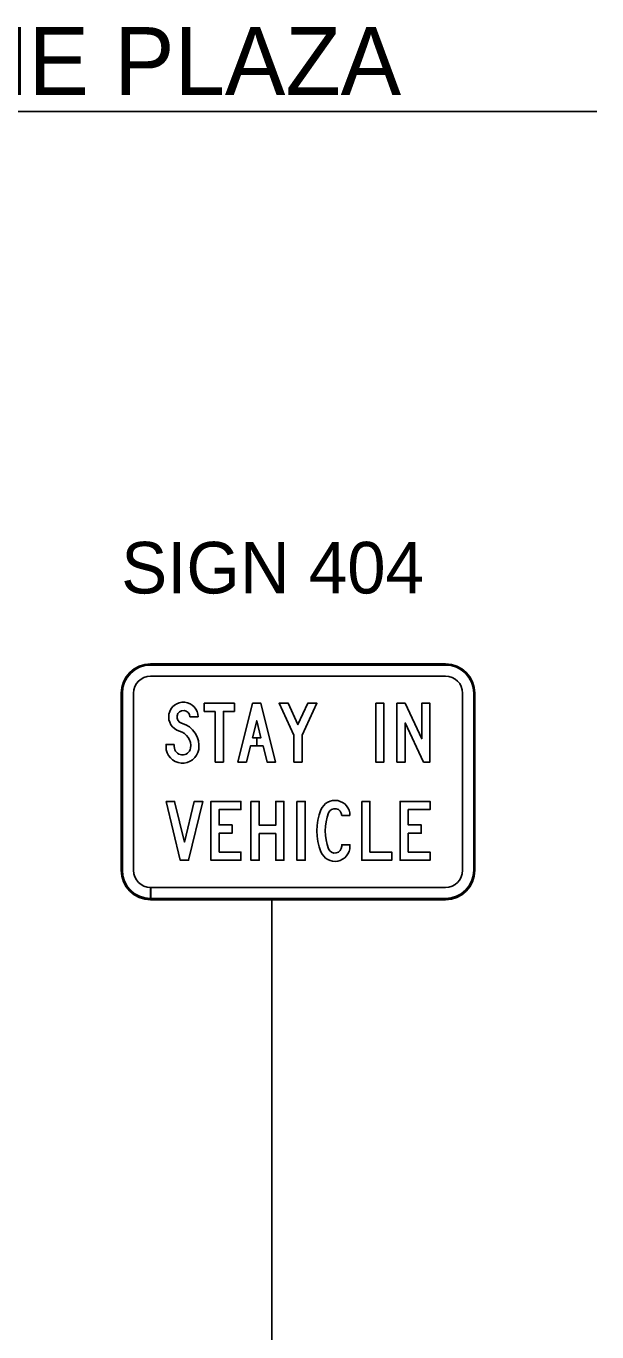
# Model space of a CAD drawing. Extents: x 524708 to 525490, y 1531861 to 1532506.
# Drawn here: x 525153.9 to 525192.6, y 1532090 to 1532178.6 of the extents above; entities that cross this region are included whole.
import ezdxf

# ---------------------------------------------------------------- set-up
doc = ezdxf.new("R2010")
doc.units = 0
for name, color, linetype in [('GSBWFill', 7, 'Continuous'), ('GSColorFill', 7, 'Continuous'), ('GSOutline', 7, 'Continuous'), ('LeaderLine_dp', 7, 'Continuous'), ('TextDetails', 7, 'Continuous'), ('TextLabel', 7, 'Continuous')]:
    doc.layers.add(name, color=color, linetype=linetype)

msp = doc.modelspace()

# ---------------------------------------------------------------- linework, layer by layer
at = {"layer": 'GSBWFill'}
for p, q in [((525164.979, 1532131.74), (525165.539, 1532131.74)), ((525163.919, 1532129.72), (525163.919, 1532129.87)), ((525175.287, 1532125.054), (525175.847, 1532125.054))]:
    msp.add_line(p, q, dxfattribs=at)
for points in [[(525166.699, 1532132.11), (525165.959, 1532132.11), (525165.959, 1532132.67), (525167.999, 1532132.67), (525167.999, 1532132.11), (525167.259, 1532132.11), (525167.259, 1532128.67), (525166.699, 1532128.67)], [(525169.519, 1532130.33), (525169.232, 1532130.33), (525169.519, 1532131.481), (525169.807, 1532130.33), (525169.52, 1532130.33), (525169.52, 1532129.77), (525169.947, 1532129.77), (525170.222, 1532128.67), (525170.799, 1532128.67), (525169.799, 1532132.67), (525169.239, 1532132.67), (525168.239, 1532128.67), (525168.817, 1532128.67), (525169.092, 1532129.77), (525169.519, 1532129.77)], [(525172.039, 1532130.49), (525172.039, 1532128.67), (525172.599, 1532128.67), (525172.599, 1532130.49), (525173.599, 1532132.67), (525172.983, 1532132.67), (525172.319, 1532131.223), (525171.655, 1532132.67), (525171.039, 1532132.67)], [(525177.599, 1532132.67), (525178.159, 1532132.67), (525178.159, 1532128.67), (525177.599, 1532128.67)], [(525180.839, 1532128.67), (525181.279, 1532128.67), (525181.279, 1532132.67), (525180.719, 1532132.67), (525180.719, 1532130.253), (525179.593, 1532132.67), (525179.039, 1532132.67), (525179.039, 1532128.67), (525179.599, 1532128.67), (525179.599, 1532131.33)], [(525163.367, 1532126.004), (525163.943, 1532126.004), (525164.607, 1532123.237), (525165.271, 1532126.004), (525165.847, 1532126.004), (525164.887, 1532122.004), (525164.327, 1532122.004)], [(525166.967, 1532122.564), (525166.967, 1532123.844), (525167.844, 1532123.844), (525167.844, 1532124.404), (525166.967, 1532124.404), (525166.967, 1532125.444), (525168.447, 1532125.444), (525168.447, 1532126.004), (525166.407, 1532126.004), (525166.407, 1532122.004), (525168.447, 1532122.004), (525168.447, 1532122.564)], [(525169.127, 1532126.004), (525169.687, 1532126.004), (525169.687, 1532124.384), (525170.807, 1532124.384), (525170.807, 1532126.004), (525171.367, 1532126.004), (525171.367, 1532122.004), (525170.807, 1532122.004), (525170.807, 1532123.824), (525169.687, 1532123.824), (525169.687, 1532122.004), (525169.127, 1532122.004)], [(525172.247, 1532126.004), (525172.807, 1532126.004), (525172.807, 1532122.004), (525172.247, 1532122.004)], [(525176.647, 1532126.004), (525177.207, 1532126.004), (525177.207, 1532122.564), (525178.687, 1532122.564), (525178.687, 1532122.004), (525176.647, 1532122.004)], [(525179.807, 1532122.564), (525179.807, 1532123.844), (525180.684, 1532123.844), (525180.684, 1532124.404), (525179.807, 1532124.404), (525179.807, 1532125.444), (525181.287, 1532125.444), (525181.287, 1532126.004), (525179.247, 1532126.004), (525179.247, 1532122.004), (525181.287, 1532122.004), (525181.287, 1532122.564)]]:
    msp.add_lwpolyline(points, close=True, dxfattribs=at)
for points in [[(525163.919, 1532129.87), (525163.359, 1532129.87), (525163.359, 1532129.72)], [(525175.847, 1532122.954), (525175.847, 1532123.064), (525175.287, 1532123.064), (525175.287, 1532122.954)]]:
    msp.add_lwpolyline(points, dxfattribs=at)
for centre, radius, start, end in [((525164.539, 1532131.74), 1, 0, 254.22594), ((525164.539, 1532131.74), 0.44, 0, 254.22594), ((525163.979, 1532129.758), 1.62, 352.12977, 74.22594), ((525163.979, 1532129.758), 1.06, 352.58042, 74.22594), ((525164.479, 1532129.72), 1.12, 180, 350.53133), ((525164.479, 1532129.72), 0.56, 180, 349.78566), ((525174.827, 1532125.054), 1.02, 0, 158.43141), ((525177.484, 1532124.004), 3.876, 158.43141, 201.5686), ((525177.484, 1532124.004), 3.316, 158.4314, 201.56859), ((525174.827, 1532125.054), 0.46, 0, 158.43141), ((525174.827, 1532122.954), 1.02, 201.56859, 0), ((525174.827, 1532122.954), 0.46, 201.56859, 0)]:
    msp.add_arc(centre, radius, start, end, dxfattribs=at)
at = {"layer": 'GSColorFill'}
for p, q in [((525182.331, 1532135.345), (525162.315, 1532135.345)), ((525182.331, 1532135.345), (525162.315, 1532135.345)), ((525182.331, 1532135.345), (525162.315, 1532135.345)), ((525162.315, 1532135.262), (525182.331, 1532135.262)), ((525162.315, 1532134.512), (525182.331, 1532134.512)), ((525160.315, 1532133.345), (525160.315, 1532121.329)), ((525160.315, 1532133.345), (525160.315, 1532121.329)), ((525160.315, 1532133.345), (525160.315, 1532121.329)), ((525160.399, 1532121.329), (525160.399, 1532133.345)), ((525161.149, 1532121.329), (525161.149, 1532133.345)), ((525183.498, 1532133.345), (525183.498, 1532121.329)), ((525184.248, 1532133.345), (525184.248, 1532121.329)), ((525184.331, 1532121.329), (525184.331, 1532133.345)), ((525184.331, 1532121.329), (525184.331, 1532133.345)), ((525184.331, 1532121.329), (525184.331, 1532133.345)), ((525164.979, 1532131.74), (525165.539, 1532131.74)), ((525163.919, 1532129.72), (525163.919, 1532129.87)), ((525175.287, 1532125.054), (525175.847, 1532125.054)), ((525162.315, 1532119.329), (525162.315, 1532120.162)), ((525162.315, 1532119.329), (525162.315, 1532119.412)), ((525182.331, 1532119.412), (525162.316, 1532119.412)), ((525162.316, 1532119.412), (525162.316, 1532119.329)), ((525182.331, 1532120.162), (525162.324, 1532120.162)), ((525162.324, 1532120.162), (525162.324, 1532119.329)), ((525162.315, 1532119.329), (525182.331, 1532119.329)), ((525162.316, 1532119.329), (525182.331, 1532119.329)), ((525162.324, 1532119.329), (525182.331, 1532119.329))]:
    msp.add_line(p, q, dxfattribs=at)
for points in [[(525166.699, 1532132.11), (525165.959, 1532132.11), (525165.959, 1532132.67), (525167.999, 1532132.67), (525167.999, 1532132.11), (525167.259, 1532132.11), (525167.259, 1532128.67), (525166.699, 1532128.67)], [(525169.519, 1532130.33), (525169.232, 1532130.33), (525169.519, 1532131.481), (525169.807, 1532130.33), (525169.52, 1532130.33), (525169.52, 1532129.77), (525169.947, 1532129.77), (525170.222, 1532128.67), (525170.799, 1532128.67), (525169.799, 1532132.67), (525169.239, 1532132.67), (525168.239, 1532128.67), (525168.817, 1532128.67), (525169.092, 1532129.77), (525169.519, 1532129.77)], [(525172.039, 1532130.49), (525172.039, 1532128.67), (525172.599, 1532128.67), (525172.599, 1532130.49), (525173.599, 1532132.67), (525172.983, 1532132.67), (525172.319, 1532131.223), (525171.655, 1532132.67), (525171.039, 1532132.67)], [(525177.599, 1532132.67), (525178.159, 1532132.67), (525178.159, 1532128.67), (525177.599, 1532128.67)], [(525180.839, 1532128.67), (525181.279, 1532128.67), (525181.279, 1532132.67), (525180.719, 1532132.67), (525180.719, 1532130.253), (525179.593, 1532132.67), (525179.039, 1532132.67), (525179.039, 1532128.67), (525179.599, 1532128.67), (525179.599, 1532131.33)], [(525163.367, 1532126.004), (525163.943, 1532126.004), (525164.607, 1532123.237), (525165.271, 1532126.004), (525165.847, 1532126.004), (525164.887, 1532122.004), (525164.327, 1532122.004)], [(525166.967, 1532122.564), (525166.967, 1532123.844), (525167.844, 1532123.844), (525167.844, 1532124.404), (525166.967, 1532124.404), (525166.967, 1532125.444), (525168.447, 1532125.444), (525168.447, 1532126.004), (525166.407, 1532126.004), (525166.407, 1532122.004), (525168.447, 1532122.004), (525168.447, 1532122.564)], [(525169.127, 1532126.004), (525169.687, 1532126.004), (525169.687, 1532124.384), (525170.807, 1532124.384), (525170.807, 1532126.004), (525171.367, 1532126.004), (525171.367, 1532122.004), (525170.807, 1532122.004), (525170.807, 1532123.824), (525169.687, 1532123.824), (525169.687, 1532122.004), (525169.127, 1532122.004)], [(525172.247, 1532126.004), (525172.807, 1532126.004), (525172.807, 1532122.004), (525172.247, 1532122.004)], [(525176.647, 1532126.004), (525177.207, 1532126.004), (525177.207, 1532122.564), (525178.687, 1532122.564), (525178.687, 1532122.004), (525176.647, 1532122.004)], [(525179.807, 1532122.564), (525179.807, 1532123.844), (525180.684, 1532123.844), (525180.684, 1532124.404), (525179.807, 1532124.404), (525179.807, 1532125.444), (525181.287, 1532125.444), (525181.287, 1532126.004), (525179.247, 1532126.004), (525179.247, 1532122.004), (525181.287, 1532122.004), (525181.287, 1532122.564)]]:
    msp.add_lwpolyline(points, close=True, dxfattribs=at)
for points in [[(525163.919, 1532129.87), (525163.359, 1532129.87), (525163.359, 1532129.72)], [(525175.847, 1532122.954), (525175.847, 1532123.064), (525175.287, 1532123.064), (525175.287, 1532122.954)]]:
    msp.add_lwpolyline(points, dxfattribs=at)
for centre, radius, start, end in [((525162.315, 1532133.345), 2, 90, 180), ((525162.315, 1532133.345), 2, 90, 180), ((525162.315, 1532133.345), 2, 90, 180), ((525162.315, 1532133.345), 1.917, 90, 180), ((525162.315, 1532133.345), 1.167, 90, 180), ((525182.331, 1532133.345), 2, 0, 90), ((525182.331, 1532133.345), 2, 0, 90), ((525182.331, 1532133.345), 2, 0, 90), ((525182.331, 1532133.345), 1.917, 0, 90), ((525182.331, 1532133.345), 1.167, 0, 90), ((525164.539, 1532131.74), 1, 0, 254.22594), ((525164.539, 1532131.74), 0.44, 0, 254.22594), ((525163.979, 1532129.758), 1.62, 352.12977, 74.22594), ((525163.979, 1532129.758), 1.06, 352.58042, 74.22594), ((525164.479, 1532129.72), 1.12, 180, 350.53133), ((525164.479, 1532129.72), 0.56, 180, 349.78566), ((525174.827, 1532125.054), 1.02, 0, 158.43141), ((525177.484, 1532124.004), 3.876, 158.43141, 201.5686), ((525177.484, 1532124.004), 3.316, 158.4314, 201.56859), ((525174.827, 1532125.054), 0.46, 0, 158.43141), ((525174.827, 1532122.954), 1.02, 201.56859, 0), ((525174.827, 1532122.954), 0.46, 201.56859, 0), ((525162.315, 1532121.329), 2, 180, 270), ((525162.315, 1532121.329), 2, 180, 270), ((525162.315, 1532121.329), 2, 180, 270), ((525162.315, 1532121.329), 1.917, 180, 270), ((525162.315, 1532121.329), 1.167, 180, 270), ((525182.331, 1532121.329), 2, 270, 0), ((525182.331, 1532121.329), 1.167, 270, 0), ((525182.331, 1532121.329), 2, 270, 0), ((525182.331, 1532121.329), 1.917, 270, 0), ((525182.331, 1532121.329), 2, 270, 0)]:
    msp.add_arc(centre, radius, start, end, dxfattribs=at)
at = {"layer": 'GSOutline'}
for p, q in [((525164.979, 1532131.74), (525165.539, 1532131.74)), ((525163.919, 1532129.72), (525163.919, 1532129.87)), ((525175.287, 1532125.054), (525175.847, 1532125.054))]:
    msp.add_line(p, q, dxfattribs=at)
for points in [[(525166.699, 1532132.11), (525165.959, 1532132.11), (525165.959, 1532132.67), (525167.999, 1532132.67), (525167.999, 1532132.11), (525167.259, 1532132.11), (525167.259, 1532128.67), (525166.699, 1532128.67)], [(525169.092, 1532129.77), (525169.947, 1532129.77), (525170.222, 1532128.67), (525170.799, 1532128.67), (525169.799, 1532132.67), (525169.239, 1532132.67), (525168.239, 1532128.67), (525168.817, 1532128.67)], [(525172.039, 1532130.49), (525172.039, 1532128.67), (525172.599, 1532128.67), (525172.599, 1532130.49), (525173.599, 1532132.67), (525172.983, 1532132.67), (525172.319, 1532131.223), (525171.655, 1532132.67), (525171.039, 1532132.67)], [(525177.599, 1532132.67), (525178.159, 1532132.67), (525178.159, 1532128.67), (525177.599, 1532128.67)], [(525180.839, 1532128.67), (525181.279, 1532128.67), (525181.279, 1532132.67), (525180.719, 1532132.67), (525180.719, 1532130.253), (525179.593, 1532132.67), (525179.039, 1532132.67), (525179.039, 1532128.67), (525179.599, 1532128.67), (525179.599, 1532131.33)], [(525169.807, 1532130.33), (525169.519, 1532131.481), (525169.232, 1532130.33)], [(525163.367, 1532126.004), (525163.943, 1532126.004), (525164.607, 1532123.237), (525165.271, 1532126.004), (525165.847, 1532126.004), (525164.887, 1532122.004), (525164.327, 1532122.004)], [(525166.967, 1532122.564), (525166.967, 1532123.844), (525167.844, 1532123.844), (525167.844, 1532124.404), (525166.967, 1532124.404), (525166.967, 1532125.444), (525168.447, 1532125.444), (525168.447, 1532126.004), (525166.407, 1532126.004), (525166.407, 1532122.004), (525168.447, 1532122.004), (525168.447, 1532122.564)], [(525169.127, 1532126.004), (525169.687, 1532126.004), (525169.687, 1532124.384), (525170.807, 1532124.384), (525170.807, 1532126.004), (525171.367, 1532126.004), (525171.367, 1532122.004), (525170.807, 1532122.004), (525170.807, 1532123.824), (525169.687, 1532123.824), (525169.687, 1532122.004), (525169.127, 1532122.004)], [(525172.247, 1532126.004), (525172.807, 1532126.004), (525172.807, 1532122.004), (525172.247, 1532122.004)], [(525176.647, 1532126.004), (525177.207, 1532126.004), (525177.207, 1532122.564), (525178.687, 1532122.564), (525178.687, 1532122.004), (525176.647, 1532122.004)], [(525179.807, 1532122.564), (525179.807, 1532123.844), (525180.684, 1532123.844), (525180.684, 1532124.404), (525179.807, 1532124.404), (525179.807, 1532125.444), (525181.287, 1532125.444), (525181.287, 1532126.004), (525179.247, 1532126.004), (525179.247, 1532122.004), (525181.287, 1532122.004), (525181.287, 1532122.564)]]:
    msp.add_lwpolyline(points, close=True, dxfattribs=at)
for points in [[(525163.919, 1532129.87), (525163.359, 1532129.87), (525163.359, 1532129.72)], [(525175.847, 1532122.954), (525175.847, 1532123.064), (525175.287, 1532123.064), (525175.287, 1532122.954)]]:
    msp.add_lwpolyline(points, dxfattribs=at)
for centre, radius, start, end in [((525164.539, 1532131.74), 1, 0, 254.22594), ((525164.539, 1532131.74), 0.44, 0, 254.22594), ((525163.979, 1532129.758), 1.62, 352.12977, 74.22594), ((525163.979, 1532129.758), 1.06, 352.58042, 74.22594), ((525164.479, 1532129.72), 1.12, 180, 350.53133), ((525164.479, 1532129.72), 0.56, 180, 349.78566), ((525174.827, 1532125.054), 1.02, 0, 158.43141), ((525177.484, 1532124.004), 3.876, 158.43141, 201.5686), ((525177.484, 1532124.004), 3.316, 158.4314, 201.56859), ((525174.827, 1532125.054), 0.46, 0, 158.43141), ((525174.827, 1532122.954), 1.02, 201.56859, 0), ((525174.827, 1532122.954), 0.46, 201.56859, 0)]:
    msp.add_arc(centre, radius, start, end, dxfattribs=at)
at = {"layer": 'LeaderLine_dp'}
msp.add_line((525170.535, 1532119.36), (525170.535, 1532065.541), dxfattribs=at)
at = {"layer": 'TextDetails'}
msp.add_line((525099.656, 1532172.851), (525192.614, 1532172.852), dxfattribs=at)

# ---------------------------------------------------------------- texts
msp.add_text('TYPICAL MAINLINE PLAZA', height=4.59999, rotation=0.00014, dxfattribs=at).set_placement((525101.723, 1532173.971))
at = {"layer": 'TextLabel'}
msp.add_text('SIGN 404', height=3.5, dxfattribs=at).set_placement((525160.317, 1532140.122))

doc.saveas('drawing.dxf')
